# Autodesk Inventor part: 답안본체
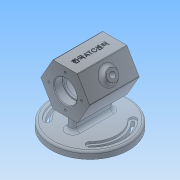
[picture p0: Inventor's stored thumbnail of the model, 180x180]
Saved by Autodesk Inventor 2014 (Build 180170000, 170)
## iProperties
Created: 2017-06
Part Number: 답안본체
Material: 일반
Document SubType Name: Modeling
Designer: NET
Density: 1 g/cm^3
Appearance: 기본값
Author: NET
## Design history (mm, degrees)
sketch "스케치1"
  geometry: C1 r 55 at (0, 0); 1 further point
  constraints: 1 centre point, 1 coincident
  dimensions: "d0" = 110 diameter of C1
extrude "돌출1" new body sketch "스케치1" distance "d1" = 10; taper "d2" = 0 deg
sketch "스케치2"
  geometry: L1 (0, 0)-(0, 62); L2 (0, 62)-(-35, 62); L3 (-35, 62)-(-35, 92); L4 (-35, 92)-(35, 92); L5 (35, 92)-(35, 62); L6 (35, 62)-(0, 62); L7 (-35, 62)-(-23, 62); L8 (-23, 62)-(-23, 77.7); L9 (-23.3, 78)-(-35, 78); L10 (0, 62)-(-20, 62); L11 (-20, 62)-(-20, 84); L12 (-17, 87)-(17, 87); L13 (20, 84)-(20, 62); L14 (35, 62)-(23, 62); L15 (23, 62)-(23, 77.7); L16 (23.3, 78)-(35, 78); L17 (23, 62)-(23, 76); L18 (23, 76)-(20, 76); L19 (-23, 62)-(-23, 76); L20 (-23, 76)-(-20, 76); A1 r 3 centre (-17, 84) between (-17, 87) and (-20, 84); A2 r 3 centre (17, 84) between (20, 84) and (17, 87); A3 r 0.3 centre (-23.3, 77.7) between (-23, 77.7) and (-23.3, 78); A4 r 0.3 centre (23.3, 77.7) between (23.3, 78) and (23, 77.7); 4 further points
  constraints: 40 end point, 18 point on line, 10 perpendicular, 8 point on circle, 8 tangent, 4 centre point, 4 parallel, 2 equal radius, 1 vertical
  dimensions: "d3" = 62 distance of L1.start L1.end; "d4" = 35 distance of L1.end L2.end; "d5" = 30 distance of L2.end L3.end; "d6" = 70 distance of L3.end L4.end; "d7" = 12 distance of L2.end L7.end; "d8" = 16 distance of L7.end point (-23, 78); "d9" = 20 distance of L1.end L10.end; "d10" = 25 distance of L10.end point (-20, 87); "d11" = 40 distance of point (-20, 87) point (20, 87); "d12" = 12 distance of L5.end L14.end; "d13" = 16 distance of L14.end point (23, 78); "d14" = 14 distance of L14.end L17.end; "d15" = 14 distance of L7.end L19.end; "d16" = 3 radius of A1; "d102" = 0.3 radius of A3
revolve "회전1" sketch "스케치2" stored, may be unused: angle "d17" = 90 deg
sketch "스케치3"
  geometry: L1 (0, 0)-(0, 50); L2 (0, 0)-(-16.273, 39.288); L3 (0, 30)-(-12.426, 30); L4 (17.179, 30.081)-(34.641, 0.163); L5 (34.641, 0.163)-(17.462, -29.918); L6 (17.462, -29.918)-(-17.179, -30.081); L7 (-17.179, -30.081)-(-34.641, -0.163); L8 (-34.641, -0.163)-(-17.462, 29.918); L9 (-17.462, 29.918)-(17.179, 30.081); 2 further points
  constraints: 18 end point, 2 point on line, 1 coincident, 1 horizontal, 1 perpendicular, 1 vertical, 1 vertical alignment, 14 other
  dimensions: "d18" = 50 distance of L1.start L1.end; "d19" = 22.5 deg angle of L1 L2; "d20" = 30 distance from line of L9 point (0, 0); "d21" = 17.17898 horizontal distance of L7.end L8.end
extrude "돌출2" join sketch "스케치3" distance "d22" = 70; taper "d23" = 0 deg
sketch "스케치5"
  geometry: L1 (0, 0)-(0, -24); L2 (0, 0)-(0, 24); L3 (-5, -24)-(-5, 24); L4 (5, -24)-(5, 24); C1 r 55 at (0, 0) reference; A1 r 5 centre (0, -24) between (-5, -24) and (5, -24); A2 r 5 centre (0, 24) between (-5, 24) and (5, 24)
  constraints: 8 end point, 4 point on circle, 2 centre point, 2 coincident, 2 equal length, 2 tangent, 1 vertical
  dimensions: "d58" = 24 distance of L1.start L1.end; "d59" = 10 diameter of A1; "d60" = 24 distance of L1.start L2.end; "d61" = 10 diameter of A2; "d62" = 10 distance between parallel lines of L4 L3
extrude "돌출4" join sketch "스케치5" stored distance "d63" = 10; taper "d64" = 0 deg
sketch "스케치6"
  geometry: L1 (30, -17.321)-(0, 0) reference; L2 (30, 51.962)-(60, 34.641) reference; L3 (45, 43.301)-(15, -8.66); L4 (0, 34.641)-(60, 0); C1 r 16 at (30, 17.321) reference; C2 r 2.5 at (41.5, 37.239); C3 r 2.5 at (10.081, 28.821); C4 r 2.5 at (18.5, -2.598); C5 r 2.5 at (49.919, 5.821); A1 r 23 centre (30, 17.321) between (41.5, 37.239) and (10.081, 28.821); 1 further point
  constraints: 5 centre point, 4 end point, 4 point on circle, 4 point on line, 2 midpoint, 1 coincident, 1 perpendicular
  dimensions: "d66" = 46 diameter of A1; "d67" = 5 diameter of C2; "d68" = 5 diameter of C3; "d69" = 5 diameter of C4; "d70" = 5 diameter of C5
hole "구멍1" sketch "스케치6" at (41.5, 37.239), (10.081, 28.821), (18.5, -2.598), (49.919, 5.821) diameter "d71" = 3.242; stored, may be unused: countersink angle "d75" = 90 deg, drill point angle "d77" = 118 deg; dims "d72" = 8, "d73" = 4, "d74" = 2, "d76" = 10
sketch "스케치7" dims "d78" = 46
  geometry: L1 (0, 0)-(30, -17.321) reference; L2 (60, 34.641)-(30, 51.962) reference; L3 (45, 43.301)-(15, -8.66); L4 (0, 34.641)-(60, 0); C1 r 16 at (30, 17.321) reference; C2 r 2 at (18.5, -2.598); C3 r 2 at (49.919, 5.821); C4 r 2 at (41.5, 37.239); C5 r 2 at (10.081, 28.821); 2 further points
  constraints: 4 centre point, 4 end point, 2 midpoint, 1 coincident, 1 perpendicular, 1 point on line, 12 other
  dimensions: "d79" = 4 diameter of C2; "d82" = 360 deg dimension on point (30, 17.321) C2.centre (derived)
hole "구멍2" sketch "스케치7" at (18.5, -2.598), (49.919, 5.821), (41.5, 37.239), (10.081, 28.821) diameter "d84" = 3.242; stored, may be unused: countersink angle "d88" = 90 deg, drill point angle "d90" = 118 deg; dims "d85" = 8, "d86" = 4, "d87" = 2, "d89" = 10
sketch "스케치8"
  geometry: L1 (0, 0)-(0, 70) reference; L2 (0, 0)-(0, 35); L3 (-17.321, 70)-(0, 70) reference; L4 (-17.321, 0)-(-17.321, 70) reference; L5 (-17.321, 0)-(0, 0) reference; L6 (0, 0)-(0, 70) reference; L7 (-17.321, 35)-(17.679, 35); 2 further points
  constraints: 4 end point, 2 midpoint, 1 coincident, 1 perpendicular, 1 other
  dimensions: "d91" = 35 distance of L1.start L2.end; "d92" = 35 distance of L7.start L7.end
feature "엠보싱1" sketch "스케치8" dims "d93" = 0.5, "d94" = 0
sketch "스케치9"
  geometry: L1 (0, 0)-(34.641, 0) reference; L2 (34.641, 0)-(34.641, 70) reference; L3 (17.321, 0)-(17.321, 35); C1 r 8 at (17.321, 35); 1 further point
  constraints: 2 end point, 1 centre point, 1 coincident, 1 midpoint, 1 parallel
  dimensions: "d95" = 35 distance of L3.start L3.end; "d96" = 16 diameter of C1
extrude "돌출5" join sketch "스케치9" distance "d97" = 7; taper "d98" = 0 deg
sketch "스케치10"
  geometry: C1 r 8 at (0, 0) reference; C2 r 4 at (0, 0); 1 further point
  constraints: 1 centre point, 1 coincident
  dimensions: "d99" = 8 diameter of C2
extrude "돌출6" cut sketch "스케치10" stored distance "d100" = 7; taper "d101" = 0 deg
sketch "스케치11" dims "d117" = 4, "d118" = 4, "d119" = 4
  geometry: L1 (-5, -24)-(-5, 24) reference; L2 (-55, 0)-(55, 0); L3 (-26.87, 26.87)-(-45.953, 45.953); L4 (-26.87, -26.87)-(-33.941, -33.941); L5 (26.87, 26.87)-(33.941, 33.941); L6 (26.87, -26.87)-(33.941, -33.941); C1 r 48 at (0, 0); C2 r 5 at (-30.406, 30.406); A1 r 55 centre (0, 0) between (-55, 0) and (55, 0) reference; A2 r 5 centre (-30.406, -30.406) between (-33.941, -33.941) and (-26.87, -26.87); A3 r 5 centre (30.406, -30.406) between (26.87, -26.87) and (33.941, -33.941); A4 r 5 centre (30.406, 30.406) between (33.941, 33.941) and (26.87, 26.87); A5 r 2 centre (-30.406, -30.406) between (-28.991, -28.991) and (-28.959, -31.787); A6 r 38 centre (0, 0) between (26.87, -26.87) and (26.87, 26.87); A7 r 38 centre (0, 0) between (-26.87, 26.87) and (-26.87, -26.87); A8 r 41 centre (0, 0) between (28.991, -28.991) and (28.991, 28.991); A9 r 41 centre (0, 0) between (-28.991, 28.991) and (-28.991, -28.991); A10 r 43 centre (0, 0) between (28.959, -31.787) and (28.959, 31.787); A11 r 43 centre (0, 0) between (-28.959, 31.787) and (-28.959, -31.787); A12 r 45 centre (0, 0) between (31.82, -31.82) and (31.82, 31.82); A13 r 45 centre (0, 0) between (-31.82, 31.82) and (-31.82, -31.82); 4 further points
  constraints: 31 point on circle, 14 centre point, 10 coincident, 10 end point, 7 point on line, 3 midpoint, 1 perpendicular, 9 other
  dimensions: "d105" = 96 diameter of C1; "d106" = 110 distance of L2.start L2.end; "d108" = 10 diameter of A2; "d113" = 10 diameter of A3; "d115" = 10 diameter of A4; "d116" = 4 diameter of A5; "d122" = 19.08317 horizontal distance of L3.start L3.end; "d125" = 19.08317 horizontal distance of L3.start L3.end; "d127" = 38 radius of A6; "d128" = 41 radius of A8; "d129" = 43 radius of A10; "d130" = 45 radius of A12; "d131" = 38 radius of A7; "d132" = 41 radius of A9; "d133" = 43 radius of A11; "d134" = 45 radius of A13
extrude "돌출7" cut sketch "스케치11" stored distance "d135" = 7; taper "d136" = 0 deg
sketch "스케치12"
  geometry: L1 (-5, -24)-(-5, 24) reference; L2 (0, -55)-(0, 55); L3 (-55, 0)-(55, 0); L4 (28.991, -28.991)-(31.82, -31.82); L5 (28.991, 28.991)-(31.82, 31.82); A1 r 45 centre (0, 0) between (-31.82, 31.82) and (-31.82, -31.82) reference; A2 r 2 centre (-30.406, 30.406) between (-28.991, 28.991) and (-31.82, 31.82) reference; A3 r 2 centre (-30.406, -30.406) between (-31.82, -31.82) and (-28.991, -28.991) reference; A4 r 55 centre (0, 0) between (0, -55) and (0, 55) reference; A5 r 2 centre (30.406, -30.406) between (28.991, -28.991) and (31.82, -31.82); A6 r 2 centre (30.406, 30.406) between (31.82, 31.82) and (28.991, 28.991); A7 r 41 centre (0, 0) between (-28.991, 28.991) and (-28.991, -28.991); A8 r 41 centre (0, 0) between (28.991, -28.991) and (28.991, 28.991); A9 r 41 centre (0, 0) between (-28.991, 28.991) and (-28.991, -28.991); A10 r 45 centre (0, 0) between (31.82, -31.82) and (31.82, 31.82)
  constraints: 20 point on circle, 8 end point, 6 centre point, 2 coincident, 2 midpoint, 1 parallel, 1 perpendicular
  dimensions: "d137" = 110 distance of L2.start L2.end; "d141" = 4 diameter of A6; "d142" = 4 diameter of A5; "d143" = 110 distance of L3.start L3.end; "d144" = 30.40559 horizontal distance of A1.centre A5.centre; "d145" = 30.40559 distance from line of A6.centre L2; "d147" = 30.40559 distance from line of L3 A5.centre; "d148" = 41 radius of A8; "d149" = 45 radius of A10
extrude "돌출8" cut sketch "스케치12" stored distance "d150" = 7; taper "d151" = 0 deg
sketch "스케치13"
  geometry: C1 r 55 at (0, 0) reference; A1 r 45 centre (0, 0) between (31.82, -31.82) and (31.82, 31.82) reference; A2 r 2 centre (30.406, -30.406) between (28.991, -28.991) and (31.82, -31.82) reference; A3 r 41 centre (0, 0) between (28.991, -28.991) and (28.991, 28.991) reference; A4 r 2 centre (30.406, 30.406) between (31.82, 31.82) and (28.991, 28.991) reference; A5 r 2 centre (-30.406, 30.406) between (-28.991, 28.991) and (-31.82, 31.82) reference; A6 r 2 centre (-30.406, -30.406) between (-31.82, -31.82) and (-28.991, -28.991) reference; A7 r 5 centre (-30.406, -30.406) between (-26.87, -26.87) and (-33.941, -33.941); A8 r 5 centre (-30.406, 30.406) between (-26.87, 26.87) and (-33.941, 33.941); A9 r 5 centre (30.406, 30.406) between (26.87, 26.87) and (33.941, 33.941); A10 r 5 centre (30.406, -30.406) between (26.87, -26.87) and (33.941, -33.941); A11 r 38 centre (0, 0) between (26.87, -26.87) and (26.87, 26.87); A12 r 38 centre (0, 0) between (-26.87, 26.87) and (-26.87, -26.87); A13 r 48 centre (0, 0) between (33.941, -33.941) and (33.941, 33.941); A14 r 48 centre (0, 0) between (-33.941, 33.941) and (-33.941, -33.941)
  constraints: 16 point on circle, 8 centre point, 6 coincident
  dimensions: "d154" = 10 diameter of A7; "d155" = 10 diameter of A8; "d156" = 10 diameter of A9; "d157" = 10 diameter of A10; "d158" = 38 radius of A12; "d159" = 38 radius of A11; "d160" = 48 radius of A13; "d161" = 48 radius of A14
extrude "돌출9" cut sketch "스케치13" distance "d162" = 3; taper "d163" = 0 deg
chamfer "모따기1" distance "d164" = 1; stored, may be unused: second distance "d165" = 2, angle "d166" = 45 deg
chamfer "모따기2" distance "d167" = 1; stored, may be unused: second distance "d168" = 2, angle "d169" = 45 deg
fillet "모깎기1" dims "d170" = 1
fillet "모깎기2" dims "d171" = 3
fillet "모깎기3" dims "d172" = 5
fillet "모깎기4" dims "d173" = 5
node "솔리드1"
node "투영된 루프2"
other parameters: "d24" = 86, "d25" = 96, "d26" = 76, "d28" = 45 deg, "d29" = 45 deg, "d34" = 43, "d35" = 43, "d50" = 86, "d103" = 86, "d104" = 76, "d107" = 45 deg, "d109" = 45 deg, "d112" = 45 deg, "d114" = 45 deg, "d121" = 82, "d139" = 45 deg, "d140" = 45 deg, "d152" = 96, "d153" = 76
